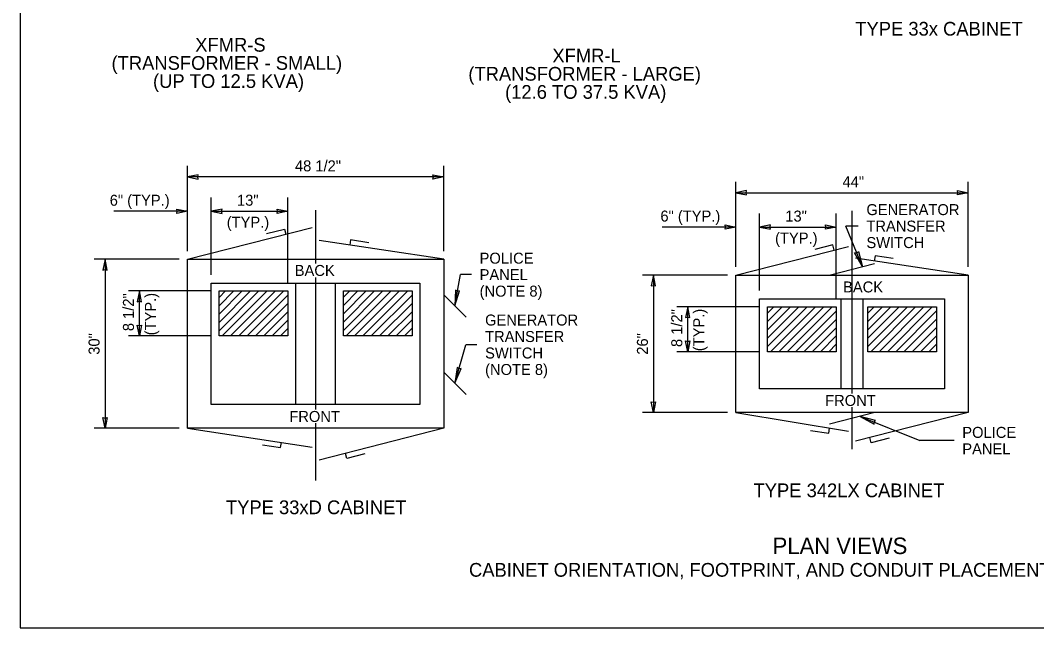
# Model space of a CAD drawing. Extents: x 99862 to 103151, y 100000 to 117076.
# Drawn here: x 99862 to 101342, y 100000 to 100884 of the extents above; entities that cross this region are included whole.
import ezdxf

# ---------------------------------------------------------------- set-up
doc = ezdxf.new("R2010")
doc.units = 0
for name, color, linetype in [('Level 1', 7, 'Continuous'), ('Level 12', 7, 'Continuous'), ('Level 15', 7, 'Continuous'), ('Level 20', 7, 'Continuous'), ('Level 25', 7, 'Continuous'), ('Level 60', 7, 'Continuous')]:
    doc.layers.add(name, color=color, linetype=linetype)

msp = doc.modelspace()

# ---------------------------------------------------------------- linework, layer by layer
at = {"layer": 'Level 1'}
for p, q in [((100105.4, 100536), (100287, 100582.3)), ((100220.5, 100573.3), (100246.6, 100579.9)), ((100246.6, 100579.9), (100248.5, 100572.5)), ((100478.6, 100536), (100297, 100563.2)), ((100342.9, 100564.1), (100341.7, 100556.5)), ((100369.5, 100560.1), (100342.9, 100564.1)), ((100263.1, 100324.4), (100263.1, 100501.4)), ((100263.1, 100324.4), (100263.1, 100501.4)), ((100320.8, 100324.4), (100320.8, 100501.4)), ((100320.8, 100324.4), (100320.8, 100501.4)), ((100511.2, 100451.8), (100478.6, 100484.4)), ((100511.2, 100339.2), (100478.6, 100371.8)), ((100105.4, 100289.8), (100287, 100262.6)), ((100478.6, 100289.8), (100297, 100243.5)), ((100214.5, 100265.6), (100241.1, 100261.7)), ((100241.1, 100261.7), (100242.3, 100269.3)), ((100337.4, 100245.8), (100335.5, 100253.3)), ((100363.5, 100252.5), (100337.4, 100245.8))]:
    msp.add_line(p, q, dxfattribs=at)
for points in [[(99862, 99999.5), (103151, 99999.5), (103151, 102075.5), (99862, 102075.5)], [(100105.4, 100536), (100478.6, 100536), (100478.6, 100289.8), (100105.4, 100289.8)], [(100140, 100501.4), (100444, 100501.4), (100444, 100324.4), (100140, 100324.4)]]:
    msp.add_lwpolyline(points, close=True, dxfattribs=at)
at = {"layer": 'Level 12'}
for p, q in [((100903.9, 100512.9), (101068.1, 100554.7)), ((101045.2, 100556.8), (101019.1, 100550.2)), ((101047.1, 100549.4), (101045.2, 100556.8)), ((101106.6, 100541), (101105.5, 100533.4)), ((101133.2, 100537), (101106.6, 100541)), ((101039.9, 100512.9), (101105.9, 100529.7)), ((101242.3, 100512.9), (101078.1, 100537.5)), ((101057.1, 100347.5), (101057.1, 100478.3)), ((101089.2, 100347.5), (101089.2, 100478.3)), ((100903.9, 100312.8), (101068.1, 100285.6)), ((101106.4, 100312.8), (101040.4, 100296)), ((101242.3, 100312.8), (101078.1, 100271)), ((101039.3, 100282.6), (101040.5, 100290.2)), ((101012.7, 100286.5), (101039.3, 100282.6)), ((101101.1, 100268.9), (101099.2, 100276.4)), ((101127.2, 100275.6), (101101.1, 100268.9))]:
    msp.add_line(p, q, dxfattribs=at)
for points in [[(100903.9, 100512.9), (101242.3, 100512.9), (101242.3, 100312.8), (100903.9, 100312.8)], [(100938.6, 100478.3), (101207.7, 100478.3), (101207.7, 100347.5), (100938.6, 100347.5)]]:
    msp.add_lwpolyline(points, close=True, dxfattribs=at)
at = {"layer": 'Level 15'}
for p, q in [((100105.4, 100548), (100105.4, 100672)), ((100478.6, 100548), (100478.6, 100672)), ((100478.6, 100656), (100105.4, 100656)), ((100903.9, 100524.9), (100903.9, 100648.9)), ((101242.3, 100524.9), (101242.3, 100648.9)), ((100903.9, 100632.9), (101242.3, 100632.9)), ((100140, 100513.4), (100140, 100625.8)), ((100251.6, 100501.8), (100251.6, 100625.8)), ((100105.4, 100606), (99998.3, 100606)), ((100140, 100606), (100251.6, 100606)), ((100292, 100607.4), (100292, 100529.7)), ((100938.6, 100490.3), (100938.6, 100602.8)), ((101050.1, 100478.7), (101050.1, 100602.8)), ((101073.1, 100606.6), (101073.1, 100340.4)), ((100903.9, 100582.9), (100796.9, 100582.9)), ((100938.6, 100582.9), (101050.1, 100582.9)), ((101082.1, 100584.3), (101064.2, 100584.3)), ((101088.3, 100525.2), (101064.2, 100584.3)), ((100093.4, 100536), (99969.4, 100536)), ((99985.4, 100536), (99985.4, 100289.8)), ((100292, 100509.7), (100292, 100317.1)), ((100494.9, 100468.1), (100502.8, 100513.6)), ((100518.8, 100513.6), (100502.8, 100513.6)), ((100891.9, 100512.9), (100767.9, 100512.9)), ((100783.9, 100512.9), (100783.9, 100312.8)), ((100139.6, 100489.8), (100019.4, 100489.8)), ((100035.4, 100424.4), (100035.4, 100489.8)), ((100938.1, 100466.7), (100817.9, 100466.7)), ((100833.9, 100401.3), (100833.9, 100466.7)), ((100139.6, 100424.4), (100019.4, 100424.4)), ((100494.9, 100355.5), (100510.8, 100411.5)), ((100526.8, 100411.5), (100510.8, 100411.5)), ((100938.1, 100401.3), (100817.9, 100401.3)), ((101073.1, 100320.4), (101073.1, 100259.6)), ((100891.9, 100312.8), (100767.9, 100312.8)), ((101085.2, 100307.1), (101171.7, 100271.9)), ((100093.4, 100289.8), (99969.4, 100289.8)), ((100292, 100297.1), (100292, 100213.8)), ((101221.7, 100271.9), (101171.7, 100271.9))]:
    msp.add_line(p, q, dxfattribs=at)
for points in [[(100105.4, 100656), (100121.1, 100652.9), (100120.4, 100656), (100121.1, 100659.1)], [(100105.4, 100656), (100121.1, 100652.9), (100120.4, 100656), (100121.1, 100659.1)], [(100478.6, 100656), (100462.9, 100652.9), (100463.6, 100656), (100462.9, 100659.1)], [(100478.6, 100656), (100462.9, 100652.9), (100463.6, 100656), (100462.9, 100659.1)], [(100903.9, 100632.9), (100919.7, 100629.8), (100918.9, 100632.9), (100919.7, 100636)], [(100903.9, 100632.9), (100919.7, 100629.8), (100918.9, 100632.9), (100919.7, 100636)], [(101242.3, 100632.9), (101226.6, 100629.8), (101227.3, 100632.9), (101226.6, 100636)], [(101242.3, 100632.9), (101226.6, 100629.8), (101227.3, 100632.9), (101226.6, 100636)], [(100105.4, 100606), (100089.7, 100602.9), (100090.4, 100606), (100089.7, 100609.1)], [(100140, 100606), (100155.7, 100602.9), (100155, 100606), (100155.7, 100609.1)], [(100251.6, 100606), (100235.9, 100602.9), (100236.6, 100606), (100235.9, 100609.1)], [(100903.9, 100582.9), (100888.2, 100579.8), (100888.9, 100582.9), (100888.2, 100586)], [(100938.6, 100582.9), (100954.3, 100579.8), (100953.6, 100582.9), (100954.3, 100586)], [(101050.1, 100582.9), (101034.4, 100579.8), (101035.1, 100582.9), (101034.4, 100586)], [(101088.3, 100525.2), (101076.9, 100545.3), (101080.1, 100545.4), (101082.4, 100547.5)], [(99985.4, 100536), (99982.3, 100520.3), (99985.4, 100521), (99988.5, 100520.3)], [(100783.9, 100512.9), (100780.8, 100497.2), (100783.9, 100497.9), (100787, 100497.2)], [(100035.4, 100489.8), (100032.3, 100474.1), (100035.4, 100474.8), (100038.5, 100474.1)], [(100494.9, 100468.1), (100501.7, 100490.1), (100498.6, 100489.6), (100495.9, 100491.1)], [(100833.9, 100466.7), (100830.8, 100451), (100833.9, 100451.7), (100837, 100451)], [(100035.4, 100424.4), (100032.3, 100440.1), (100035.4, 100439.4), (100038.5, 100440.1)], [(100833.9, 100401.3), (100830.8, 100417.1), (100833.9, 100416.3), (100837, 100417.1)], [(100494.9, 100355.5), (100504, 100376.7), (100500.8, 100376.5), (100498.3, 100378.3)], [(100783.9, 100312.8), (100780.8, 100328.6), (100783.9, 100327.8), (100787, 100328.6)], [(99985.4, 100289.8), (99982.3, 100305.5), (99985.4, 100304.8), (99988.5, 100305.5)], [(101085.2, 100307.1), (101105.2, 100295.7), (101105.4, 100298.9), (101107.5, 100301.2)]]:
    msp.add_lwpolyline(points, close=True, dxfattribs=at)
at = {"layer": 'Level 25'}
for p, q in [((100151.6, 100480.4), (100161, 100489.8)), ((100151.6, 100468.3), (100173.1, 100489.8)), ((100151.6, 100456.2), (100185.2, 100489.8)), ((100151.6, 100444.1), (100197.3, 100489.8)), ((100151.6, 100432), (100209.3, 100489.8)), ((100156, 100424.4), (100221.4, 100489.8)), ((100168.1, 100424.4), (100233.5, 100489.8)), ((100180.2, 100424.4), (100245.6, 100489.8)), ((100192.3, 100424.4), (100251.6, 100483.7)), ((100251.6, 100489.8), (100251.6, 100424.4)), ((100332.4, 100424.4), (100332.4, 100489.8)), ((100332.4, 100468.5), (100353.7, 100489.8)), ((100332.4, 100456.4), (100365.8, 100489.8)), ((100332.4, 100444.3), (100377.9, 100489.8)), ((100332.4, 100432.2), (100390, 100489.8)), ((100332.4, 100480.6), (100341.7, 100489.8)), ((100336.7, 100424.4), (100402.1, 100489.8)), ((100348.8, 100424.4), (100414.2, 100489.8)), ((100360.9, 100424.4), (100426.3, 100489.8)), ((100373, 100424.4), (100432.4, 100483.9)), ((100204.4, 100424.4), (100251.6, 100471.6)), ((100385.1, 100424.4), (100432.4, 100471.8)), ((100950.1, 100457.3), (100959.5, 100466.7)), ((100950.1, 100445.2), (100971.6, 100466.7)), ((100950.1, 100433.1), (100983.7, 100466.7)), ((100950.1, 100421), (100995.8, 100466.7)), ((100950.1, 100409), (101007.9, 100466.7)), ((100954.6, 100401.3), (101020, 100466.7)), ((100966.7, 100401.3), (101032.1, 100466.7)), ((100978.8, 100401.3), (101044.2, 100466.7)), ((101050.1, 100466.7), (101050.1, 100401.3)), ((101096.1, 100401.3), (101096.1, 100466.7)), ((101096.1, 100445.4), (101117.5, 100466.7)), ((101096.1, 100433.3), (101129.6, 100466.7)), ((101096.1, 100421.2), (101141.7, 100466.7)), ((101096.1, 100409.1), (101153.8, 100466.7)), ((101096.1, 100457.5), (101105.4, 100466.7)), ((101100.4, 100401.3), (101165.8, 100466.7)), ((101112.5, 100401.3), (101177.9, 100466.7)), ((101124.6, 100401.3), (101190, 100466.7)), ((100216.5, 100424.4), (100251.6, 100459.5)), ((100397.2, 100424.4), (100432.4, 100459.7)), ((100990.8, 100401.3), (101050.1, 100460.6)), ((101136.7, 100401.3), (101196.2, 100460.8)), ((100228.6, 100424.4), (100251.6, 100447.4)), ((100240.7, 100424.4), (100251.6, 100435.3)), ((100409.3, 100424.4), (100432.4, 100447.6)), ((100421.3, 100424.4), (100432.4, 100435.5)), ((101002.9, 100401.3), (101050.1, 100448.5)), ((101015, 100401.3), (101050.1, 100436.4)), ((101148.8, 100401.3), (101196.2, 100448.7)), ((101160.9, 100401.3), (101196.2, 100436.6)), ((100251.6, 100424.4), (100151.6, 100424.4)), ((100432.4, 100424.4), (100332.4, 100424.4)), ((101027.1, 100401.3), (101050.1, 100424.3)), ((101173, 100401.3), (101196.2, 100424.5)), ((101039.2, 100401.3), (101050.1, 100412.3)), ((101185.1, 100401.3), (101196.2, 100412.4)), ((101050.1, 100401.3), (100950.1, 100401.3)), ((101196.2, 100401.3), (101096.1, 100401.3))]:
    msp.add_line(p, q, dxfattribs=at)
for points in [[(100151.6, 100424.4), (100151.6, 100489.8), (100251.6, 100489.8)], [(100332.4, 100489.8), (100432.4, 100489.8), (100432.4, 100424.4)], [(100950.1, 100401.3), (100950.1, 100466.7), (101050.1, 100466.7)], [(101096.1, 100466.7), (101196.2, 100466.7), (101196.2, 100401.3)]]:
    msp.add_lwpolyline(points, dxfattribs=at)
at = {"layer": 'Level 60'}
msp.add_line((99862, 99999.5), (99862, 99999.5), dxfattribs=at)

# ---------------------------------------------------------------- texts
at = {"layer": 'Level 20'}
for s, height, p in [('TYPE 33x CABINET', 20, (101077.9, 100861.7)), ('XFMR-S', 20, (100116.7, 100838.3)), ('XFMR-L', 20, (100636.8, 100822.6)), ('(TRANSFORMER - SMALL)', 20, (99994.8, 100811.9)), ('(UP TO 12.5 KVA)', 20, (100055.2, 100785.5)), ('(TRANSFORMER - LARGE)', 20, (100514.4, 100796.1)), ('(12.6 TO 37.5 KVA)', 20, (100567.9, 100769.7)), ('48 1/2"', 16, (100261.9, 100664)), ('44"', 16, (101059.3, 100640.9)), ('6" (TYP.)', 16, (99992.2, 100614)), ('13"', 16, (100177.5, 100614)), ('GENERATOR', 16, (101094.1, 100600.3)), ('(TYP.)', 16, (100162.6, 100582)), ('6" (TYP.)', 16, (100794.1, 100590.9)), ('13"', 16, (100976, 100590.9)), ('TRANSFER', 16, (101094.1, 100576.3)), ('(TYP.)', 16, (100961.1, 100558.9)), ('SWITCH', 16, (101094.1, 100552.3)), ('BACK', 16, (100261.6, 100511.7)), ('BACK', 16, (101060.1, 100487.7)), ('FRONT', 16, (101034, 100322.4)), ('FRONT', 16, (100253.7, 100299.1)), ('TYPE 342LX CABINET', 20, (100929.7, 100189.5)), ('TYPE 33xD CABINET', 20, (100161.4, 100164.8)), ('PLAN VIEWS', 24, (100957.5, 100106.7)), ('CABINET ORIENTATION, FOOTPRINT, AND CONDUIT PLACEMENT LOCATIONS', 20, (100515.4, 100073.7))]:
    msp.add_text(s, height=height, dxfattribs=at).set_placement(p)
for s, rotation, p in [('POLICE', 360, (100530.8, 100529.6)), ('PANEL', 360, (100530.8, 100505.6)), ('(NOTE 8)', 360, (100530.8, 100481.6)), ('8 1/2"', 90, (100027.4, 100431.3)), ('(TYP.)', 90, (100059.4, 100425.2)), ('GENERATOR', 360, (100538.8, 100439.5)), ('8 1/2"', 90, (100825.9, 100408.2)), ('(TYP.)', 90, (100857.9, 100402.1)), ('30"', 90, (99977.4, 100397)), ('TRANSFER', 360, (100538.8, 100415.5)), ('26"', 90, (100775.9, 100397)), ('SWITCH', 360, (100538.8, 100391.5)), ('(NOTE 8)', 360, (100538.8, 100367.5)), ('POLICE', 360, (101233.7, 100275.9)), ('PANEL', 360, (101233.7, 100251.9))]:
    msp.add_text(s, height=16, rotation=rotation, dxfattribs=at).set_placement(p)

doc.saveas('drawing.dxf')
